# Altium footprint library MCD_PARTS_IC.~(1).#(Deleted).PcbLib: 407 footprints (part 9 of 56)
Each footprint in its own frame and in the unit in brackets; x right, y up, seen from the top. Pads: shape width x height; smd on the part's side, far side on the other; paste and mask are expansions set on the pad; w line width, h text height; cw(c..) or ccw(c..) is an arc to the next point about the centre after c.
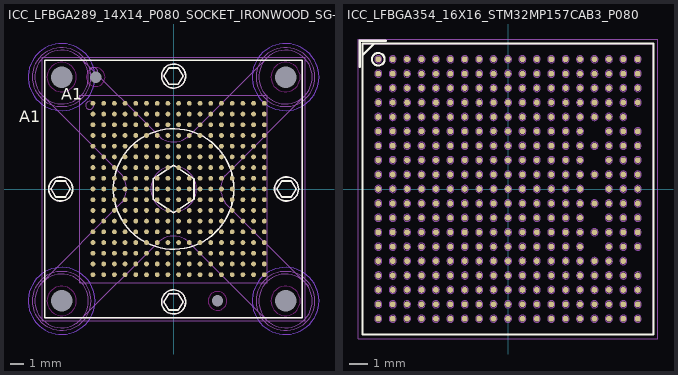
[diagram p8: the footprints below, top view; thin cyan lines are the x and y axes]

## ICC_LFBGA289_14X14_P080_SOCKET_IRONWOOD_SG-BGA-6112MF [mm] "MCD-02237"
height 8.25
pads (295):
  round 0.36 smd mask+0.05: A1(-6.025,6.4) A2(-5.225,6.4) A3(-4.425,6.4) A4(-3.625,6.4) A5(-2.825,6.4) A6(-2.025,6.4) A7(-1.225,6.4) A8(-0.425,6.4) A9(0.375,6.4) A10(1.175,6.4) A11(1.975,6.4) A12(2.775,6.4) A13(3.575,6.4) A14(4.375,6.4) A15(5.175,6.4) A16(5.975,6.4) A17(6.775,6.4) B1(-6.025,5.6) B2(-5.225,5.6) B3(-4.425,5.6) B4(-3.625,5.6) B5(-2.825,5.6) B6(-2.025,5.6) B7(-1.225,5.6) B8(-0.425,5.6) B9(0.375,5.6) B10(1.175,5.6) B11(1.975,5.6) B12(2.775,5.6) B13(3.575,5.6) B14(4.375,5.6) B15(5.175,5.6) B16(5.975,5.6) B17(6.775,5.6) C1(-6.025,4.8) C2(-5.225,4.8) C3(-4.425,4.8) C4(-3.625,4.8) C5(-2.825,4.8) C6(-2.025,4.8) C7(-1.225,4.8) C8(-0.425,4.8) C9(0.375,4.8) C10(1.175,4.8) C11(1.975,4.8) C12(2.775,4.8) C13(3.575,4.8) C14(4.375,4.8) C15(5.175,4.8) C16(5.975,4.8) C17(6.775,4.8) D1(-6.025,4) D2(-5.225,4) D3(-4.425,4) D4(-3.625,4) D5(-2.825,4) D6(-2.025,4) D7(-1.225,4) D8(-0.425,4) D9(0.375,4) D10(1.175,4) D11(1.975,4) D12(2.775,4) D13(3.575,4) D14(4.375,4) D15(5.175,4) D16(5.975,4) D17(6.775,4) E1(-6.025,3.2) E2(-5.225,3.2) E3(-4.425,3.2) E4(-3.625,3.2) E5(-2.825,3.2) E6(-2.025,3.2) E7(-1.225,3.2) E8(-0.425,3.2) E9(0.375,3.2) E10(1.175,3.2) E11(1.975,3.2) E12(2.775,3.2) E13(3.575,3.2) E14(4.375,3.2) E15(5.175,3.2) E16(5.975,3.2) E17(6.775,3.2) F1(-6.025,2.4) F2(-5.225,2.4) F3(-4.425,2.4) F4(-3.625,2.4) F5(-2.825,2.4) F6(-2.025,2.4) F7(-1.225,2.4) F8(-0.425,2.4) F9(0.375,2.4) F10(1.175,2.4) F11(1.975,2.4) F12(2.775,2.4) F13(3.575,2.4) F14(4.375,2.4) F15(5.175,2.4) F16(5.975,2.4) F17(6.775,2.4) G1(-6.025,1.6) G2(-5.225,1.6) G3(-4.425,1.6) G4(-3.625,1.6) G5(-2.825,1.6) G6(-2.025,1.6) G7(-1.225,1.6) G8(-0.425,1.6) G9(0.375,1.6) G10(1.175,1.6) G11(1.975,1.6) G12(2.775,1.6) G13(3.575,1.6) G14(4.375,1.6) G15(5.175,1.6) G16(5.975,1.6) G17(6.775,1.6) H1(-6.025,0.8) H2(-5.225,0.8) H3(-4.425,0.8) H4(-3.625,0.8) H5(-2.825,0.8) H6(-2.025,0.8) H7(-1.225,0.8) H8(-0.425,0.8) H9(0.375,0.8) H10(1.175,0.8) H11(1.975,0.8) H12(2.775,0.8) H13(3.575,0.8) H14(4.375,0.8) H15(5.175,0.8) H16(5.975,0.8) H17(6.775,0.8) J1(-6.025,0) J2(-5.225,0) J3(-4.425,0) J4(-3.625,0) J5(-2.825,0) J6(-2.025,0) J7(-1.225,0) J8(-0.425,0) J9(0.375,0) J10(1.175,0) J11(1.975,0) J12(2.775,0) J13(3.575,0) J14(4.375,0) J15(5.175,0) J16(5.975,0) J17(6.775,0) K1(-6.025,-0.8) K2(-5.225,-0.8) K3(-4.425,-0.8) K4(-3.625,-0.8) K5(-2.825,-0.8) K6(-2.025,-0.8) K7(-1.225,-0.8) K8(-0.425,-0.8) K9(0.375,-0.8) K10(1.175,-0.8) K11(1.975,-0.8) K12(2.775,-0.8) K13(3.575,-0.8) K14(4.375,-0.8) K15(5.175,-0.8) K16(5.975,-0.8) K17(6.775,-0.8) L1(-6.025,-1.6) L2(-5.225,-1.6) L3(-4.425,-1.6) L4(-3.625,-1.6) L5(-2.825,-1.6) L6(-2.025,-1.6) L7(-1.225,-1.6) L8(-0.425,-1.6) L9(0.375,-1.6) L10(1.175,-1.6) L11(1.975,-1.6) L12(2.775,-1.6) L13(3.575,-1.6) L14(4.375,-1.6) L15(5.175,-1.6) L16(5.975,-1.6) L17(6.775,-1.6) M1(-6.025,-2.4) M2(-5.225,-2.4) M3(-4.425,-2.4) M4(-3.625,-2.4) M5(-2.825,-2.4) M6(-2.025,-2.4) M7(-1.225,-2.4) M8(-0.425,-2.4) M9(0.375,-2.4) M10(1.175,-2.4) M11(1.975,-2.4) M12(2.775,-2.4) M13(3.575,-2.4) M14(4.375,-2.4) M15(5.175,-2.4) M16(5.975,-2.4) M17(6.775,-2.4) N1(-6.025,-3.2) N2(-5.225,-3.2) N3(-4.425,-3.2) N4(-3.625,-3.2) N5(-2.825,-3.2) N6(-2.025,-3.2) N7(-1.225,-3.2) N8(-0.425,-3.2) N9(0.375,-3.2) N10(1.175,-3.2) N11(1.975,-3.2) N12(2.775,-3.2) N13(3.575,-3.2) N14(4.375,-3.2) N15(5.175,-3.2) N16(5.975,-3.2) N17(6.775,-3.2) P1(-6.025,-4) P2(-5.225,-4) P3(-4.425,-4) P4(-3.625,-4) P5(-2.825,-4) P6(-2.025,-4) P7(-1.225,-4) P8(-0.425,-4) P9(0.375,-4) P10(1.175,-4) P11(1.975,-4) P12(2.775,-4) P13(3.575,-4) P14(4.375,-4) P15(5.175,-4) P16(5.975,-4) P17(6.775,-4) R1(-6.025,-4.8) R2(-5.225,-4.8) R3(-4.425,-4.8) R4(-3.625,-4.8) R5(-2.825,-4.8) R6(-2.025,-4.8) R7(-1.225,-4.8) R8(-0.425,-4.8) R9(0.375,-4.8) R10(1.175,-4.8) R11(1.975,-4.8) R12(2.775,-4.8) R13(3.575,-4.8) R14(4.375,-4.8) R15(5.175,-4.8) R16(5.975,-4.8) R17(6.775,-4.8) T1(-6.025,-5.6) T2(-5.225,-5.6) T3(-4.425,-5.6) T4(-3.625,-5.6) T5(-2.825,-5.6) T6(-2.025,-5.6) T7(-1.225,-5.6) T8(-0.425,-5.6) T9(0.375,-5.6) T10(1.175,-5.6) T11(1.975,-5.6) T12(2.775,-5.6) T13(3.575,-5.6) T14(4.375,-5.6) T15(5.175,-5.6) T16(5.975,-5.6) T17(6.775,-5.6) U1(-6.025,-6.4) U2(-5.225,-6.4) U3(-4.425,-6.4) U4(-3.625,-6.4) U5(-2.825,-6.4) U6(-2.025,-6.4) U7(-1.225,-6.4) U8(-0.425,-6.4) U9(0.375,-6.4) U10(1.175,-6.4) U11(1.975,-6.4) U12(2.775,-6.4) U13(3.575,-6.4) U14(4.375,-6.4) U15(5.175,-6.4) U16(5.975,-6.4) u17(6.775,-6.4)
  round 0 hole 1.61 unplated mask+0.05: NPTH1(-8.363,8.363) NPTH2(8.363,8.363) NPTH3(8.363,-8.363) NPTH4(-8.363,-8.363)
  round 0 hole 0.85 unplated mask+0.05: NPTH5(3.283,-8.363) NPTH6(-5.823,8.363)
Bottom Layer keep-out:
  circle w0.01: c-8.363,-8.363 r2.5
  circle w0.01: c8.363,-8.363 r2.5
  circle w0.01: c8.363,8.363 r2.5
  circle w0.01: c-8.362,8.362 r2.5
Top Overlay:
  circle w0.12: c0,8.437 r0.9
  circle w0.12: c8.438,0 r0.9
  circle w0.12: c0,-8.438 r0.9
  circle w0.12: c-8.438,0 r0.9
  circle w0.12: c0,0 r4.5
  lines w0.12: -9.613,-9.613 -9.613,9.613 9.613,9.613 9.613,-9.613 -9.613,-9.613 ; -9.158,0 -8.798,-0.6 -8.078,-0.6 -7.718,0 -8.078,0.6 -8.798,0.6 -9.158,0 ; -1.524,-0.762 -1.524,0.762 0,1.778 1.524,0.762 1.524,-0.762 0,-1.778 -1.524,-0.762 ; -0.72,-8.438 -0.36,-9.038 0.36,-9.038 0.72,-8.438 0.36,-7.838 -0.36,-7.838 -0.72,-8.438 ; -0.72,8.437 -0.36,9.037 0.36,9.037 0.72,8.437 0.36,7.837 -0.36,7.837 -0.72,8.437 ; 7.718,0 8.078,-0.6 8.798,-0.6 9.158,0 8.798,0.6 8.078,0.6 7.718,0
  text "A1" at -11.55,4.675 h1.5
  text "A1" at -8.4,6.375 h1.5
Bottom Overlay:
  circle w0.12: c8.363,8.363 r2.5
  circle w0.12: c8.362,-8.362 r2.5
  circle w0.12: c-8.362,-8.362 r2.5
  circle w0.12: c-8.363,8.363 r2.5
Keep-Out Layer:
  circle w0.01: c3.283,-8.363 r0.7
  circle w0.01: c-8.363,-8.363 r1.1
  circle w0.01: c8.362,-8.362 r1.1
  circle w0.01: c8.363,8.363 r1.1
  circle w0.01: c-8.362,8.362 r1.1
  circle w0.01: c-5.823,8.363 r0.7
M14-Top Assembly:
  circle w0.01: c-6.275,6.25 r0.3
  circle w0.01: c-5.975,8.775 r0.3
  circle w0.01: c0,8.437 r0.9
  circle w0.01: c8.438,0 r0.9
  circle w0.01: c0,-8.438 r0.9
  circle w0.01: c-8.438,0 r0.9
  circle w0.01: c0,0 r4.5
  lines w0.01: -9.613,-9.613 -9.613,9.613 9.613,9.613 9.613,3.562 9.613,-9.613 -9.613,-9.613 ; -9.158,0 -8.798,0.6 -8.078,0.6 -7.718,0 -8.078,-0.6 -8.798,-0.6 -9.158,0 ; -7,-7 -7,7 7,7 7,-7 -7,-7 ; -1.524,-0.762 -1.524,0.762 0,1.778 1.524,0.762 1.524,-0.762 0,-1.778 -1.524,-0.762 ; -0.72,-8.438 -0.36,-7.838 0.36,-7.838 0.72,-8.438 0.36,-9.038 -0.36,-9.038 -0.72,-8.438 ; -0.72,8.437 -0.36,7.837 0.36,7.837 0.72,8.437 0.36,9.037 -0.36,9.037 -0.72,8.437 ; 7.718,0 8.078,0.6 8.798,0.6 9.158,0 8.798,-0.6 8.078,-0.6 7.718,0
  text "'.Designator'" at 0,0 h0.75
M15-Bottom Assembly:
  circle w0.01: c8.362,8.362 r2
  circle w0.01: c8.363,-8.363 r2
  circle w0.01: c-8.362,-8.362 r2
  circle w0.01: c-8.362,8.362 r2
  lines w0.01: -10.044,7.235 -3.82,1.011 ; -9.929,-7.075 -3.82,-0.967 ; -7.235,-10.044 -1.011,-3.82 ; -7.075,9.929 -0.967,3.82 ; -3.848,1.029 cw(c-5.325,0) -3.826,-0.996 ; -1.029,-3.848 cw(c0,-5.325) 0.996,-3.826 ; -0.996,3.826 ccw(c0,5.325) 1.029,3.848 ; 0.967,-3.82 7.075,-9.929 ; 1.011,3.82 7.235,10.044 ; 3.82,-1.011 10.044,-7.235 ; 3.82,0.967 9.928,7.075 ; 3.826,0.996 ccw(c5.325,0) 3.848,-1.029
M16-Top Courtyard:
  lines w0.01: -9.825,-9.825 9.825,-9.825 9.825,9.825 -9.825,9.825 -9.825,-9.825
M17-Bottom Courtyard:
  circle w0.01: c-8.362,-8.362 r2.2
  circle w0.01: c8.362,-8.362 r2.2
  circle w0.01: c8.362,8.362 r2.2
  circle w0.01: c-8.362,8.362 r2.2
  circle w0.01: c0,0 r1.7
3D body: height 5, standoff 0, extent -9.613,-9.613 9.613,9.613
3D body: height 9.86, standoff 9.85, extent -1.025,-1.212 1.025,1.213
3D body: height 9.85, standoff 1.6, extent -2.5,-2.497 2.5,2.497
3D body: height 6.01, standoff 6, extent -0.72,-9.038 0.72,-7.838
3D body: height 6, standoff 5, extent -0.893,-9.336 0.9,-7.539
3D body: height 6.01, standoff 6, extent 7.717,-0.6 9.158,0.6
3D body: height 6, standoff 5, extent 7.545,-0.898 9.338,0.898
3D body: height 6.01, standoff 6, extent -0.72,7.837 0.72,9.037
3D body: height 6, standoff 5, extent -0.893,7.539 0.9,9.336
3D body: height 6.01, standoff 6, extent -9.158,-0.6 -7.718,0.6
3D body: height 6, standoff 5, extent -9.33,-0.898 -7.537,0.898
3D body: height -4.1, standoff -6.6, extent -10.044,-10.044 10.044,10.044
3D body: height -1.6, standoff -6.6, extent -1.5,-1.5 1.5,1.5
3D body: height -1.6, standoff -6.6, extent -10.375,-8.363 -6.362,-6.35
3D body: height -1.6, standoff -6.6, extent -10.375,-10.363 -6.363,-8.35
3D body: height -1.6, standoff -6.6, extent 6.35,-8.363 10.363,-6.35
3D body: height -1.6, standoff -6.6, extent 6.35,-10.363 10.362,-8.35
3D body: height -1.6, standoff -6.6, extent 6.35,8.362 10.363,10.375
3D body: height -1.6, standoff -6.6, extent 6.35,6.362 10.362,8.375
3D body: height -1.6, standoff -6.6, extent -10.375,6.362 -6.363,8.375
3D body: height -1.6, standoff -6.6, extent -10.375,8.362 -6.362,10.375

## ICC_LFBGA354_16X16_STM32MP157CAB3_P080 [mm] "MCD-01805"
height 1.29
pads (354):
  round 0.32 smd paste+0 mask+0.05: A1(-7.2,7.2) A2(-6.4,7.2) A3(-5.6,7.2) A4(-4.8,7.2) A5(-4,7.2) A6(-3.2,7.2) A7(-2.4,7.2) A8(-1.6,7.2) A9(-0.8,7.2) A10(0,7.2) A11(0.8,7.2) A12(1.6,7.2) A13(2.4,7.2) A14(3.2,7.2) A15(4,7.2) A16(4.8,7.2) A17(5.6,7.2) A18(6.4,7.2) A19(7.2,7.2) B1(-7.2,6.4) B2(-6.4,6.4) B3(-5.6,6.4) B4(-4.8,6.4) B5(-4,6.4) B6(-3.2,6.4) B7(-2.4,6.4) B8(-1.6,6.4) B9(-0.8,6.4) B10(0,6.4) B11(0.8,6.4) B12(1.6,6.4) B13(2.4,6.4) B14(3.2,6.4) B15(4,6.4) B16(4.8,6.4) B17(5.6,6.4) B18(6.4,6.4) B19(7.2,6.4) C1(-7.2,5.6) C2(-6.4,5.6) C3(-5.6,5.6) C4(-4.8,5.6) C5(-4,5.6) C6(-3.2,5.6) C7(-2.4,5.6) C8(-1.6,5.6) C9(-0.8,5.6) C10(0,5.6) C11(0.8,5.6) C12(1.6,5.6) C13(2.4,5.6) C14(3.2,5.6) C15(4,5.6) C16(4.8,5.6) C17(5.6,5.6) C18(6.4,5.6) C19(7.2,5.6) D1(-7.2,4.8) D2(-6.4,4.8) D3(-5.6,4.8) D4(-4.8,4.8) D5(-4,4.8) D6(-3.2,4.8) D7(-2.4,4.8) D8(-1.6,4.8) D9(-0.8,4.8) D10(0,4.8) D11(0.8,4.8) D12(1.6,4.8) D13(2.4,4.8) D14(3.2,4.8) D15(4,4.8) D16(4.8,4.8) D17(5.6,4.8) D18(6.4,4.8) D19(7.2,4.8) E1(-7.2,4) E2(-6.4,4) E3(-5.6,4) E4(-4.8,4) E5(-4,4) E6(-3.2,4) E7(-2.4,4) E8(-1.6,4) E9(-0.8,4) E10(0,4) E11(0.8,4) E12(1.6,4) E13(2.4,4) E14(3.2,4) E15(4,4) E16(4.8,4) E17(5.6,4) E18(6.4,4) F1(-7.2,3.2) F2(-6.4,3.2) F3(-5.6,3.2) F4(-4.8,3.2) F5(-4,3.2) F6(-3.2,3.2) F7(-2.4,3.2) F8(-1.6,3.2) F9(-0.8,3.2) F10(0,3.2) F11(0.8,3.2) F12(1.6,3.2) F13(2.4,3.2) F14(3.2,3.2) F15(4,3.2) F17(5.6,3.2) F18(6.4,3.2) F19(7.2,3.2) G1(-7.2,2.4) G2(-6.4,2.4) G3(-5.6,2.4) G4(-4.8,2.4) G5(-4,2.4) G6(-3.2,2.4) G7(-2.4,2.4) G8(-1.6,2.4) G9(-0.8,2.4) G10(0,2.4) G11(0.8,2.4) G12(1.6,2.4) G13(2.4,2.4) G14(3.2,2.4) G15(4,2.4) G16(4.8,2.4) G17(5.6,2.4) G18(6.4,2.4) G19(7.2,2.4) H1(-7.2,1.6) H2(-6.4,1.6) H3(-5.6,1.6) H4(-4.8,1.6) H5(-4,1.6) H6(-3.2,1.6) H7(-2.4,1.6) H8(-1.6,1.6) H9(-0.8,1.6) H10(0,1.6) H11(0.8,1.6) H12(1.6,1.6) H13(2.4,1.6) H14(3.2,1.6) H15(4,1.6) H17(5.6,1.6) H18(6.4,1.6) H19(7.2,1.6) J1(-7.2,0.8) J2(-6.4,0.8) J3(-5.6,0.8) J4(-4.8,0.8) J5(-4,0.8) J6(-3.2,0.8) J7(-2.4,0.8) J8(-1.6,0.8) J9(-0.8,0.8) J10(0,0.8) J11(0.8,0.8) J12(1.6,0.8) J13(2.4,0.8) J14(3.2,0.8) J15(4,0.8) J16(4.8,0.8) J17(5.6,0.8) J18(6.4,0.8) J19(7.2,0.8) K1(-7.2,0) K2(-6.4,0) K3(-5.6,0) K4(-4.8,0) K5(-4,0) K6(-3.2,0) K7(-2.4,0) K8(-1.6,0) K9(-0.8,0) K10(0,0) K11(0.8,0) K12(1.6,0) K13(2.4,0) K14(3.2,0) K15(4,0) K17(5.6,0) K18(6.4,0) K19(7.2,0) L1(-7.2,-0.8) L2(-6.4,-0.8) L3(-5.6,-0.8) L4(-4.8,-0.8) L5(-4,-0.8) L6(-3.2,-0.8) L7(-2.4,-0.8) L8(-1.6,-0.8) L9(-0.8,-0.8) L10(0,-0.8) L11(0.8,-0.8) L12(1.6,-0.8) L13(2.4,-0.8) L14(3.2,-0.8) L15(4,-0.8) L16(4.8,-0.8) L17(5.6,-0.8) L18(6.4,-0.8) L19(7.2,-0.8) M1(-7.2,-1.6) M2(-6.4,-1.6) M3(-5.6,-1.6) M4(-4.8,-1.6) M5(-4,-1.6) M6(-3.2,-1.6) M7(-2.4,-1.6) M8(-1.6,-1.6) M9(-0.8,-1.6) M10(0,-1.6) M11(0.8,-1.6) M12(1.6,-1.6) M13(2.4,-1.6) M14(3.2,-1.6) M15(4,-1.6) M17(5.6,-1.6) M18(6.4,-1.6) M19(7.2,-1.6) N1(-7.2,-2.4) N2(-6.4,-2.4) N3(-5.6,-2.4) N4(-4.8,-2.4) N5(-4,-2.4) N6(-3.2,-2.4) N7(-2.4,-2.4) N8(-1.6,-2.4) N9(-0.8,-2.4) N10(0,-2.4) N11(0.8,-2.4) N12(1.6,-2.4) N13(2.4,-2.4) N14(3.2,-2.4) N15(4,-2.4) N16(4.8,-2.4) N17(5.6,-2.4) N18(6.4,-2.4) N19(7.2,-2.4) P1(-7.2,-3.2) P2(-6.4,-3.2) P3(-5.6,-3.2) P4(-4.8,-3.2) P5(-4,-3.2) P6(-3.2,-3.2) P7(-2.4,-3.2) P8(-1.6,-3.2) P9(-0.8,-3.2) P10(0,-3.2) P11(0.8,-3.2) P12(1.6,-3.2) P13(2.4,-3.2) P14(3.2,-3.2) P15(4,-3.2) P17(5.6,-3.2) P18(6.4,-3.2) P19(7.2,-3.2) R1(-7.2,-4) R2(-6.4,-4) R3(-5.6,-4) R4(-4.8,-4) R5(-4,-4) R6(-3.2,-4) R7(-2.4,-4) R8(-1.6,-4) R9(-0.8,-4) R10(0,-4) R11(0.8,-4) R12(1.6,-4) R13(2.4,-4) R14(3.2,-4) R15(4,-4) R16(4.8,-4) R17(5.6,-4) R18(6.4,-4) T1(-7.2,-4.8) T2(-6.4,-4.8) T3(-5.6,-4.8) T4(-4.8,-4.8) T5(-4,-4.8) T6(-3.2,-4.8) T7(-2.4,-4.8) T8(-1.6,-4.8) T9(-0.8,-4.8) T10(0,-4.8) T11(0.8,-4.8) T12(1.6,-4.8) T13(2.4,-4.8) T14(3.2,-4.8) T15(4,-4.8) T16(4.8,-4.8) T17(5.6,-4.8) T18(6.4,-4.8) T19(7.2,-4.8) U1(-7.2,-5.6) U2(-6.4,-5.6) U3(-5.6,-5.6) U4(-4.8,-5.6) U5(-4,-5.6) U6(-3.2,-5.6) U7(-2.4,-5.6) U8(-1.6,-5.6) U9(-0.8,-5.6) U10(0,-5.6) U11(0.8,-5.6) U12(1.6,-5.6) U13(2.4,-5.6) U14(3.2,-5.6) U15(4,-5.6) U16(4.8,-5.6) U17(5.6,-5.6) U18(6.4,-5.6) U19(7.2,-5.6) V1(-7.2,-6.4) V2(-6.4,-6.4) V3(-5.6,-6.4) V4(-4.8,-6.4) V5(-4,-6.4) V6(-3.2,-6.4) V7(-2.4,-6.4) V8(-1.6,-6.4) V9(-0.8,-6.4) V10(0,-6.4) V11(0.8,-6.4) V12(1.6,-6.4) V13(2.4,-6.4) V14(3.2,-6.4) V15(4,-6.4) V16(4.8,-6.4) V17(5.6,-6.4) V18(6.4,-6.4) V19(7.2,-6.4) W1(-7.2,-7.2) W2(-6.4,-7.2) W3(-5.6,-7.2) W4(-4.8,-7.2) W5(-4,-7.2) W6(-3.2,-7.2) W7(-2.4,-7.2) W8(-1.6,-7.2) W9(-0.8,-7.2) W10(0,-7.2) W11(0.8,-7.2) W12(1.6,-7.2) W13(2.4,-7.2) W14(3.2,-7.2) W15(4,-7.2) W16(4.8,-7.2) W17(5.6,-7.2) W18(6.4,-7.2) W19(7.2,-7.2)
Top Overlay:
  circle w0.12: c-7.2,7.2 r0.35
  lines w0.12: -8.225,6.775 -8.225,8.225 -6.775,8.225 ; -8.075,7.42 -7.42,8.075 ; -8.075,-8.075 -8.075,8.075 8.075,8.075 8.075,-8.075 -8.075,-8.075
M14-Top Assembly:
  drawing of 358 lines, arcs and shapes, not listed
  text "A1" at -7.45,7 h0.4
  text "'.Designator'" at -2,-0.5 h0.75
M16-Top Courtyard:
  lines w0.01: -8.325,-8.325 8.325,-8.325 8.325,8.325 -8.325,8.325 -8.325,-8.325
3D body: height 0.36, standoff -0.04, extent 4.601,-7.397 5,-7.003
3D body: height 0.36, standoff -0.04, extent 5.401,-7.397 5.8,-7.003
3D body: height 0.36, standoff -0.04, extent 6.201,-7.397 6.6,-7.003
3D body: height 0.36, standoff -0.04, extent 7.001,-7.397 7.4,-7.003
3D body: height 0.36, standoff -0.04, extent 4.601,-2.597 5,-2.203
3D body: height 0.36, standoff -0.04, extent 5.401,-2.597 5.8,-2.203
3D body: height 0.36, standoff -0.04, extent 6.201,-2.597 6.6,-2.203
3D body: height 0.36, standoff -0.04, extent 7.001,-2.597 7.4,-2.203
3D body: height 0.36, standoff -0.04, extent 7.001,-3.397 7.4,-3.003
3D body: height 0.36, standoff -0.04, extent 6.201,-3.397 6.6,-3.003
3D body: height 0.36, standoff -0.04, extent 5.401,-3.397 5.8,-3.003
3D body: height 0.36, standoff -0.04, extent 6.201,-4.197 6.6,-3.803
3D body: height 0.36, standoff -0.04, extent 5.401,-4.197 5.8,-3.803
3D body: height 0.36, standoff -0.04, extent 4.601,-4.197 5,-3.803
3D body: height 0.36, standoff -0.04, extent 7.001,-4.997 7.4,-4.603
3D body: height 0.36, standoff -0.04, extent 6.201,-4.997 6.6,-4.603
3D body: height 0.36, standoff -0.04, extent 5.401,-4.997 5.8,-4.603
3D body: height 0.36, standoff -0.04, extent 4.601,-4.997 5,-4.603
3D body: height 0.36, standoff -0.04, extent 7.001,-5.797 7.4,-5.403
3D body: height 0.36, standoff -0.04, extent 6.201,-5.797 6.6,-5.403
3D body: height 0.36, standoff -0.04, extent 5.401,-5.797 5.8,-5.403
3D body: height 0.36, standoff -0.04, extent 4.601,-5.797 5,-5.403
3D body: height 0.36, standoff -0.04, extent 7.001,-6.597 7.4,-6.203
3D body: height 0.36, standoff -0.04, extent 6.201,-6.597 6.6,-6.203
3D body: height 0.36, standoff -0.04, extent 5.401,-6.597 5.8,-6.203
3D body: height 0.36, standoff -0.04, extent 4.601,-6.597 5,-6.203
3D body: height 0.36, standoff -0.04, extent 4.601,2.203 5,2.597
3D body: height 0.36, standoff -0.04, extent 5.401,2.203 5.8,2.597
3D body: height 0.36, standoff -0.04, extent 6.201,2.203 6.6,2.597
3D body: height 0.36, standoff -0.04, extent 7.001,2.203 7.4,2.597
3D body: height 0.36, standoff -0.04, extent 7.001,1.403 7.4,1.797
3D body: height 0.36, standoff -0.04, extent 6.201,1.403 6.6,1.797
3D body: height 0.36, standoff -0.04, extent 5.401,1.403 5.8,1.797
3D body: height 0.36, standoff -0.04, extent 7.001,0.603 7.4,0.997
3D body: height 0.36, standoff -0.04, extent 6.201,0.603 6.6,0.997
3D body: height 0.36, standoff -0.04, extent 5.401,0.603 5.8,0.997
3D body: height 0.36, standoff -0.04, extent 4.601,0.603 5,0.997
3D body: height 0.36, standoff -0.04, extent 7.001,-0.197 7.4,0.197
3D body: height 0.36, standoff -0.04, extent 6.201,-0.197 6.6,0.197
3D body: height 0.36, standoff -0.04, extent 5.401,-0.197 5.8,0.197
3D body: height 0.36, standoff -0.04, extent 7.001,-0.997 7.4,-0.603
3D body: height 0.36, standoff -0.04, extent 6.201,-0.997 6.6,-0.603
3D body: height 0.36, standoff -0.04, extent 5.401,-0.997 5.8,-0.603
3D body: height 0.36, standoff -0.04, extent 4.601,-0.997 5,-0.603
3D body: height 0.36, standoff -0.04, extent 7.001,-1.797 7.4,-1.403
3D body: height 0.36, standoff -0.04, extent 6.201,-1.797 6.6,-1.403
3D body: height 0.36, standoff -0.04, extent 5.401,-1.797 5.8,-1.403
3D body: height 0.36, standoff -0.04, extent 3.801,-7.397 4.2,-7.003
3D body: height 0.36, standoff -0.04, extent 3.001,-7.397 3.4,-7.003
3D body: height 0.36, standoff -0.04, extent 2.201,-7.397 2.6,-7.003
3D body: height 0.36, standoff -0.04, extent 1.401,-7.397 1.8,-7.003
3D body: height 0.36, standoff -0.04, extent 0.601,-7.397 1,-7.003
3D body: height 0.36, standoff -0.04, extent -3.399,-7.397 -3,-7.003
3D body: height 0.36, standoff -0.04, extent -2.599,-7.397 -2.2,-7.003
3D body: height 0.36, standoff -0.04, extent -1.799,-7.397 -1.4,-7.003
3D body: height 0.36, standoff -0.04, extent -0.999,-7.397 -0.6,-7.003
3D body: height 0.36, standoff -0.04, extent -0.199,-7.397 0.2,-7.003
3D body: height 0.36, standoff -0.04, extent -7.399,-7.397 -7,-7.003
3D body: height 0.36, standoff -0.04, extent -6.599,-7.397 -6.2,-7.003
3D body: height 0.36, standoff -0.04, extent -5.799,-7.397 -5.4,-7.003
3D body: height 0.36, standoff -0.04, extent -4.999,-7.397 -4.6,-7.003
3D body: height 0.36, standoff -0.04, extent -4.199,-7.397 -3.8,-7.003
3D body: height 0.36, standoff -0.04, extent 3.801,-2.597 4.2,-2.203
3D body: height 0.36, standoff -0.04, extent 3.001,-2.597 3.4,-2.203
3D body: height 0.36, standoff -0.04, extent 2.201,-2.597 2.6,-2.203
3D body: height 0.36, standoff -0.04, extent 1.401,-2.597 1.8,-2.203
3D body: height 0.36, standoff -0.04, extent 0.601,-2.597 1,-2.203
3D body: height 0.36, standoff -0.04, extent -3.399,-2.597 -3,-2.203
3D body: height 0.36, standoff -0.04, extent -2.599,-2.597 -2.2,-2.203
3D body: height 0.36, standoff -0.04, extent -1.799,-2.597 -1.4,-2.203
3D body: height 0.36, standoff -0.04, extent -0.999,-2.597 -0.6,-2.203
3D body: height 0.36, standoff -0.04, extent -0.199,-2.597 0.2,-2.203
3D body: height 0.36, standoff -0.04, extent -7.399,-2.597 -7,-2.203
3D body: height 0.36, standoff -0.04, extent -6.599,-2.597 -6.2,-2.203
3D body: height 0.36, standoff -0.04, extent -5.799,-2.597 -5.4,-2.203
3D body: height 0.36, standoff -0.04, extent -4.999,-2.597 -4.6,-2.203
3D body: height 0.36, standoff -0.04, extent -4.199,-2.597 -3.8,-2.203
3D body: height 0.36, standoff -0.04, extent -4.199,-3.397 -3.8,-3.003
3D body: height 0.36, standoff -0.04, extent -4.999,-3.397 -4.6,-3.003
3D body: height 0.36, standoff -0.04, extent -5.799,-3.397 -5.4,-3.003
3D body: height 0.36, standoff -0.04, extent -6.599,-3.397 -6.2,-3.003
3D body: height 0.36, standoff -0.04, extent -7.399,-3.397 -7,-3.003
3D body: height 0.36, standoff -0.04, extent -0.199,-3.397 0.2,-3.003
3D body: height 0.36, standoff -0.04, extent -0.999,-3.397 -0.6,-3.003
3D body: height 0.36, standoff -0.04, extent -1.799,-3.397 -1.4,-3.003
3D body: height 0.36, standoff -0.04, extent -2.599,-3.397 -2.2,-3.003
3D body: height 0.36, standoff -0.04, extent -3.399,-3.397 -3,-3.003
3D body: height 0.36, standoff -0.04, extent 0.601,-3.397 1,-3.003
3D body: height 0.36, standoff -0.04, extent 1.401,-3.397 1.8,-3.003
3D body: height 0.36, standoff -0.04, extent 2.201,-3.397 2.6,-3.003
3D body: height 0.36, standoff -0.04, extent 3.001,-3.397 3.4,-3.003
3D body: height 0.36, standoff -0.04, extent 3.801,-3.397 4.2,-3.003
3D body: height 0.36, standoff -0.04, extent -4.199,-4.197 -3.8,-3.803
3D body: height 0.36, standoff -0.04, extent -4.999,-4.197 -4.6,-3.803
3D body: height 0.36, standoff -0.04, extent -5.799,-4.197 -5.4,-3.803
3D body: height 0.36, standoff -0.04, extent -6.599,-4.197 -6.2,-3.803
3D body: height 0.36, standoff -0.04, extent -7.399,-4.197 -7,-3.803
3D body: height 0.36, standoff -0.04, extent -0.199,-4.197 0.2,-3.803
3D body: height 0.36, standoff -0.04, extent -0.999,-4.197 -0.6,-3.803
3D body: height 0.36, standoff -0.04, extent -1.799,-4.197 -1.4,-3.803
3D body: height 0.36, standoff -0.04, extent -2.599,-4.197 -2.2,-3.803
3D body: height 0.36, standoff -0.04, extent -3.399,-4.197 -3,-3.803
3D body: height 0.36, standoff -0.04, extent 0.601,-4.197 1,-3.803
3D body: height 0.36, standoff -0.04, extent 1.401,-4.197 1.8,-3.803
3D body: height 0.36, standoff -0.04, extent 2.201,-4.197 2.6,-3.803
3D body: height 0.36, standoff -0.04, extent 3.001,-4.197 3.4,-3.803
3D body: height 0.36, standoff -0.04, extent 3.801,-4.197 4.2,-3.803
3D body: height 0.36, standoff -0.04, extent -4.199,-4.997 -3.8,-4.603
3D body: height 0.36, standoff -0.04, extent -4.999,-4.997 -4.6,-4.603
3D body: height 0.36, standoff -0.04, extent -5.799,-4.997 -5.4,-4.603
3D body: height 0.36, standoff -0.04, extent -6.599,-4.997 -6.2,-4.603
3D body: height 0.36, standoff -0.04, extent -7.399,-4.997 -7,-4.603
3D body: height 0.36, standoff -0.04, extent -0.199,-4.997 0.2,-4.603
3D body: height 0.36, standoff -0.04, extent -0.999,-4.997 -0.6,-4.603
3D body: height 0.36, standoff -0.04, extent -1.799,-4.997 -1.4,-4.603
3D body: height 0.36, standoff -0.04, extent -2.599,-4.997 -2.2,-4.603
3D body: height 0.36, standoff -0.04, extent -3.399,-4.997 -3,-4.603
3D body: height 0.36, standoff -0.04, extent 0.601,-4.997 1,-4.603
3D body: height 0.36, standoff -0.04, extent 1.401,-4.997 1.8,-4.603
3D body: height 0.36, standoff -0.04, extent 2.201,-4.997 2.6,-4.603
3D body: height 0.36, standoff -0.04, extent 3.001,-4.997 3.4,-4.603
3D body: height 0.36, standoff -0.04, extent 3.801,-4.997 4.2,-4.603
3D body: height 0.36, standoff -0.04, extent -4.199,-5.797 -3.8,-5.403
3D body: height 0.36, standoff -0.04, extent -4.999,-5.797 -4.6,-5.403
3D body: height 0.36, standoff -0.04, extent -5.799,-5.797 -5.4,-5.403
3D body: height 0.36, standoff -0.04, extent -6.599,-5.797 -6.2,-5.403
3D body: height 0.36, standoff -0.04, extent -7.399,-5.797 -7,-5.403
3D body: height 0.36, standoff -0.04, extent -0.199,-5.797 0.2,-5.403
3D body: height 0.36, standoff -0.04, extent -0.999,-5.797 -0.6,-5.403
3D body: height 0.36, standoff -0.04, extent -1.799,-5.797 -1.4,-5.403
3D body: height 0.36, standoff -0.04, extent -2.599,-5.797 -2.2,-5.403
3D body: height 0.36, standoff -0.04, extent -3.399,-5.797 -3,-5.403
3D body: height 0.36, standoff -0.04, extent 0.601,-5.797 1,-5.403
3D body: height 0.36, standoff -0.04, extent 1.401,-5.797 1.8,-5.403
3D body: height 0.36, standoff -0.04, extent 2.201,-5.797 2.6,-5.403
3D body: height 0.36, standoff -0.04, extent 3.001,-5.797 3.4,-5.403
3D body: height 0.36, standoff -0.04, extent 3.801,-5.797 4.2,-5.403
3D body: height 0.36, standoff -0.04, extent -4.199,-6.597 -3.8,-6.203
3D body: height 0.36, standoff -0.04, extent -4.999,-6.597 -4.6,-6.203
3D body: height 0.36, standoff -0.04, extent -5.799,-6.597 -5.4,-6.203
3D body: height 0.36, standoff -0.04, extent -6.599,-6.597 -6.2,-6.203
3D body: height 0.36, standoff -0.04, extent -7.399,-6.597 -7,-6.203
3D body: height 0.36, standoff -0.04, extent -0.199,-6.597 0.2,-6.203
3D body: height 0.36, standoff -0.04, extent -0.999,-6.597 -0.6,-6.203
3D body: height 0.36, standoff -0.04, extent -1.799,-6.597 -1.4,-6.203
3D body: height 0.36, standoff -0.04, extent -2.599,-6.597 -2.2,-6.203
3D body: height 0.36, standoff -0.04, extent -3.399,-6.597 -3,-6.203
3D body: height 0.36, standoff -0.04, extent 0.601,-6.597 1,-6.203
3D body: height 0.36, standoff -0.04, extent 1.401,-6.597 1.8,-6.203
3D body: height 0.36, standoff -0.04, extent 2.201,-6.597 2.6,-6.203
3D body: height 0.36, standoff -0.04, extent 3.001,-6.597 3.4,-6.203
3D body: height 0.36, standoff -0.04, extent 3.801,-6.597 4.2,-6.203
3D body: height 0.36, standoff -0.04, extent 3.801,2.203 4.2,2.597
3D body: height 0.36, standoff -0.04, extent 3.001,2.203 3.4,2.597
3D body: height 0.36, standoff -0.04, extent 2.201,2.203 2.6,2.597
3D body: height 0.36, standoff -0.04, extent 1.401,2.203 1.8,2.597
3D body: height 0.36, standoff -0.04, extent 0.601,2.203 1,2.597
3D body: height 0.36, standoff -0.04, extent -3.399,2.203 -3,2.597
3D body: height 0.36, standoff -0.04, extent -2.599,2.203 -2.2,2.597
3D body: height 0.36, standoff -0.04, extent -1.799,2.203 -1.4,2.597
3D body: height 0.36, standoff -0.04, extent -0.999,2.203 -0.6,2.597
3D body: height 0.36, standoff -0.04, extent -0.199,2.203 0.2,2.597
3D body: height 0.36, standoff -0.04, extent -7.399,2.203 -7,2.597
3D body: height 0.36, standoff -0.04, extent -6.599,2.203 -6.2,2.597
3D body: height 0.36, standoff -0.04, extent -5.799,2.203 -5.4,2.597
3D body: height 0.36, standoff -0.04, extent -4.999,2.203 -4.6,2.597
3D body: height 0.36, standoff -0.04, extent -4.199,2.203 -3.8,2.597
3D body: height 0.36, standoff -0.04, extent -4.199,1.403 -3.8,1.797
3D body: height 0.36, standoff -0.04, extent -4.999,1.403 -4.6,1.797
3D body: height 0.36, standoff -0.04, extent -5.799,1.403 -5.4,1.797
3D body: height 0.36, standoff -0.04, extent -6.599,1.403 -6.2,1.797
3D body: height 0.36, standoff -0.04, extent -7.399,1.403 -7,1.797
3D body: height 0.36, standoff -0.04, extent -0.199,1.403 0.2,1.797
3D body: height 0.36, standoff -0.04, extent -0.999,1.403 -0.6,1.797
3D body: height 0.36, standoff -0.04, extent -1.799,1.403 -1.4,1.797
3D body: height 0.36, standoff -0.04, extent -2.599,1.403 -2.2,1.797
3D body: height 0.36, standoff -0.04, extent -3.399,1.403 -3,1.797
3D body: height 0.36, standoff -0.04, extent 0.601,1.403 1,1.797
3D body: height 0.36, standoff -0.04, extent 1.401,1.403 1.8,1.797
3D body: height 0.36, standoff -0.04, extent 2.201,1.403 2.6,1.797
3D body: height 0.36, standoff -0.04, extent 3.001,1.403 3.4,1.797
3D body: height 0.36, standoff -0.04, extent 3.801,1.403 4.2,1.797
3D body: height 0.36, standoff -0.04, extent -4.199,0.603 -3.8,0.997
3D body: height 0.36, standoff -0.04, extent -4.999,0.603 -4.6,0.997
3D body: height 0.36, standoff -0.04, extent -5.799,0.603 -5.4,0.997
3D body: height 0.36, standoff -0.04, extent -6.599,0.603 -6.2,0.997
3D body: height 0.36, standoff -0.04, extent -7.399,0.603 -7,0.997
3D body: height 0.36, standoff -0.04, extent -0.199,0.603 0.2,0.997
3D body: height 0.36, standoff -0.04, extent -0.999,0.603 -0.6,0.997
3D body: height 0.36, standoff -0.04, extent -1.799,0.603 -1.4,0.997
3D body: height 0.36, standoff -0.04, extent -2.599,0.603 -2.2,0.997
3D body: height 0.36, standoff -0.04, extent -3.399,0.603 -3,0.997
3D body: height 0.36, standoff -0.04, extent 0.601,0.603 1,0.997
3D body: height 0.36, standoff -0.04, extent 1.401,0.603 1.8,0.997
3D body: height 0.36, standoff -0.04, extent 2.201,0.603 2.6,0.997
3D body: height 0.36, standoff -0.04, extent 3.001,0.603 3.4,0.997
3D body: height 0.36, standoff -0.04, extent 3.801,0.603 4.2,0.997
3D body: height 0.36, standoff -0.04, extent -4.199,-0.197 -3.8,0.197
3D body: height 0.36, standoff -0.04, extent -4.999,-0.197 -4.6,0.197
3D body: height 0.36, standoff -0.04, extent -5.799,-0.197 -5.4,0.197
3D body: height 0.36, standoff -0.04, extent -6.599,-0.197 -6.2,0.197
3D body: height 0.36, standoff -0.04, extent -7.399,-0.197 -7,0.197
3D body: height 0.36, standoff -0.04, extent -0.199,-0.197 0.2,0.197
3D body: height 0.36, standoff -0.04, extent -0.999,-0.197 -0.6,0.197
3D body: height 0.36, standoff -0.04, extent -1.799,-0.197 -1.4,0.197
3D body: height 0.36, standoff -0.04, extent -2.599,-0.197 -2.2,0.197
3D body: height 0.36, standoff -0.04, extent -3.399,-0.197 -3,0.197
3D body: height 0.36, standoff -0.04, extent 0.601,-0.197 1,0.197
3D body: height 0.36, standoff -0.04, extent 1.401,-0.197 1.8,0.197
3D body: height 0.36, standoff -0.04, extent 2.201,-0.197 2.6,0.197
3D body: height 0.36, standoff -0.04, extent 3.001,-0.197 3.4,0.197
3D body: height 0.36, standoff -0.04, extent 3.801,-0.197 4.2,0.197
3D body: height 0.36, standoff -0.04, extent -4.199,-0.997 -3.8,-0.603
3D body: height 0.36, standoff -0.04, extent -4.999,-0.997 -4.6,-0.603
3D body: height 0.36, standoff -0.04, extent -5.799,-0.997 -5.4,-0.603
3D body: height 0.36, standoff -0.04, extent -6.599,-0.997 -6.2,-0.603
3D body: height 0.36, standoff -0.04, extent -7.399,-0.997 -7,-0.603
3D body: height 0.36, standoff -0.04, extent -0.199,-0.997 0.2,-0.603
3D body: height 0.36, standoff -0.04, extent -0.999,-0.997 -0.6,-0.603
3D body: height 0.36, standoff -0.04, extent -1.799,-0.997 -1.4,-0.603
3D body: height 0.36, standoff -0.04, extent -2.599,-0.997 -2.2,-0.603
3D body: height 0.36, standoff -0.04, extent -3.399,-0.997 -3,-0.603
3D body: height 0.36, standoff -0.04, extent 0.601,-0.997 1,-0.603
3D body: height 0.36, standoff -0.04, extent 1.401,-0.997 1.8,-0.603
3D body: height 0.36, standoff -0.04, extent 2.201,-0.997 2.6,-0.603
3D body: height 0.36, standoff -0.04, extent 3.001,-0.997 3.4,-0.603
3D body: height 0.36, standoff -0.04, extent 3.801,-0.997 4.2,-0.603
3D body: height 0.36, standoff -0.04, extent -4.199,-1.797 -3.8,-1.403
3D body: height 0.36, standoff -0.04, extent -4.999,-1.797 -4.6,-1.403
3D body: height 0.36, standoff -0.04, extent -5.799,-1.797 -5.4,-1.403
3D body: height 0.36, standoff -0.04, extent -6.599,-1.797 -6.2,-1.403
3D body: height 0.36, standoff -0.04, extent -7.399,-1.797 -7,-1.403
3D body: height 0.36, standoff -0.04, extent -0.199,-1.797 0.2,-1.403
3D body: height 0.36, standoff -0.04, extent -0.999,-1.797 -0.6,-1.403
3D body: height 0.36, standoff -0.04, extent -1.799,-1.797 -1.4,-1.403
3D body: height 0.36, standoff -0.04, extent -2.599,-1.797 -2.2,-1.403
3D body: height 0.36, standoff -0.04, extent -3.399,-1.797 -3,-1.403
3D body: height 0.36, standoff -0.04, extent 0.601,-1.797 1,-1.403
3D body: height 0.36, standoff -0.04, extent 1.401,-1.797 1.8,-1.403
3D body: height 0.36, standoff -0.04, extent 2.201,-1.797 2.6,-1.403
3D body: height 0.36, standoff -0.04, extent 3.001,-1.797 3.4,-1.403
3D body: height 0.36, standoff -0.04, extent 3.801,-1.797 4.2,-1.403
3D body: height 0.36, standoff -0.04, extent 4.601,7.003 5,7.397
3D body: height 0.36, standoff -0.04, extent 5.401,7.003 5.8,7.397
3D body: height 0.36, standoff -0.04, extent 6.201,7.003 6.6,7.397
3D body: height 0.36, standoff -0.04, extent 7.001,7.003 7.4,7.397
3D body: height 0.36, standoff -0.04, extent 7.001,6.203 7.4,6.597
3D body: height 0.36, standoff -0.04, extent 6.201,6.203 6.6,6.597
3D body: height 0.36, standoff -0.04, extent 5.401,6.203 5.8,6.597
3D body: height 0.36, standoff -0.04, extent 4.601,6.203 5,6.597
3D body: height 0.36, standoff -0.04, extent 7.001,5.403 7.4,5.797
3D body: height 0.36, standoff -0.04, extent 6.201,5.403 6.6,5.797
3D body: height 0.36, standoff -0.04, extent 5.401,5.403 5.8,5.797
3D body: height 0.36, standoff -0.04, extent 4.601,5.403 5,5.797
3D body: height 0.36, standoff -0.04, extent 7.001,4.603 7.4,4.997
3D body: height 0.36, standoff -0.04, extent 6.201,4.603 6.6,4.997
3D body: height 0.36, standoff -0.04, extent 5.401,4.603 5.8,4.997
3D body: height 0.36, standoff -0.04, extent 4.601,4.603 5,4.997
3D body: height 0.36, standoff -0.04, extent 6.201,3.803 6.6,4.197
3D body: height 0.36, standoff -0.04, extent 5.401,3.803 5.8,4.197
3D body: height 0.36, standoff -0.04, extent 4.601,3.803 5,4.197
3D body: height 0.36, standoff -0.04, extent 7.001,3.003 7.4,3.397
3D body: height 0.36, standoff -0.04, extent 6.201,3.003 6.6,3.397
3D body: height 0.36, standoff -0.04, extent 5.401,3.003 5.8,3.397
3D body: height 0.36, standoff -0.04, extent 3.801,7.003 4.2,7.397
3D body: height 0.36, standoff -0.04, extent 3.001,7.003 3.4,7.397
3D body: height 0.36, standoff -0.04, extent 2.201,7.003 2.6,7.397
3D body: height 0.36, standoff -0.04, extent 1.401,7.003 1.8,7.397
3D body: height 0.36, standoff -0.04, extent 0.601,7.003 1,7.397
3D body: height 0.36, standoff -0.04, extent -3.399,7.003 -3,7.397
3D body: height 0.36, standoff -0.04, extent -2.599,7.003 -2.2,7.397
3D body: height 0.36, standoff -0.04, extent -1.799,7.003 -1.4,7.397
3D body: height 0.36, standoff -0.04, extent -0.999,7.003 -0.6,7.397
3D body: height 0.36, standoff -0.04, extent -0.199,7.003 0.2,7.397
3D body: height 0.36, standoff -0.04, extent -7.399,7.003 -7,7.397
3D body: height 0.36, standoff -0.04, extent -6.599,7.003 -6.2,7.397
3D body: height 0.36, standoff -0.04, extent -5.799,7.003 -5.4,7.397
3D body: height 0.36, standoff -0.04, extent -4.999,7.003 -4.6,7.397
3D body: height 0.36, standoff -0.04, extent -4.199,7.003 -3.8,7.397
3D body: height 0.36, standoff -0.04, extent -4.199,6.203 -3.8,6.597
3D body: height 0.36, standoff -0.04, extent -4.999,6.203 -4.6,6.597
3D body: height 0.36, standoff -0.04, extent -5.799,6.203 -5.4,6.597
3D body: height 0.36, standoff -0.04, extent -6.599,6.203 -6.2,6.597
3D body: height 0.36, standoff -0.04, extent -7.399,6.203 -7,6.597
3D body: height 0.36, standoff -0.04, extent -0.199,6.203 0.2,6.597
3D body: height 0.36, standoff -0.04, extent -0.999,6.203 -0.6,6.597
3D body: height 0.36, standoff -0.04, extent -1.799,6.203 -1.4,6.597
3D body: height 0.36, standoff -0.04, extent -2.599,6.203 -2.2,6.597
3D body: height 0.36, standoff -0.04, extent -3.399,6.203 -3,6.597
3D body: height 0.36, standoff -0.04, extent 0.601,6.203 1,6.597
3D body: height 0.36, standoff -0.04, extent 1.401,6.203 1.8,6.597
3D body: height 0.36, standoff -0.04, extent 2.201,6.203 2.6,6.597
3D body: height 0.36, standoff -0.04, extent 3.001,6.203 3.4,6.597
3D body: height 0.36, standoff -0.04, extent 3.801,6.203 4.2,6.597
3D body: height 0.36, standoff -0.04, extent -4.199,5.403 -3.8,5.797
3D body: height 0.36, standoff -0.04, extent -4.999,5.403 -4.6,5.797
3D body: height 0.36, standoff -0.04, extent -5.799,5.403 -5.4,5.797
3D body: height 0.36, standoff -0.04, extent -6.599,5.403 -6.2,5.797
3D body: height 0.36, standoff -0.04, extent -7.399,5.403 -7,5.797
3D body: height 0.36, standoff -0.04, extent -0.199,5.403 0.2,5.797
3D body: height 0.36, standoff -0.04, extent -0.999,5.403 -0.6,5.797
3D body: height 0.36, standoff -0.04, extent -1.799,5.403 -1.4,5.797
3D body: height 0.36, standoff -0.04, extent -2.599,5.403 -2.2,5.797
3D body: height 0.36, standoff -0.04, extent -3.399,5.403 -3,5.797
3D body: height 0.36, standoff -0.04, extent 0.601,5.403 1,5.797
3D body: height 0.36, standoff -0.04, extent 1.401,5.403 1.8,5.797
3D body: height 0.36, standoff -0.04, extent 2.201,5.403 2.6,5.797
3D body: height 0.36, standoff -0.04, extent 3.001,5.403 3.4,5.797
3D body: height 0.36, standoff -0.04, extent 3.801,5.403 4.2,5.797
3D body: height 0.36, standoff -0.04, extent -4.199,4.603 -3.8,4.997
3D body: height 0.36, standoff -0.04, extent -4.999,4.603 -4.6,4.997
3D body: height 0.36, standoff -0.04, extent -5.799,4.603 -5.4,4.997
3D body: height 0.36, standoff -0.04, extent -6.599,4.603 -6.2,4.997
3D body: height 0.36, standoff -0.04, extent -7.399,4.603 -7,4.997
3D body: height 0.36, standoff -0.04, extent -0.199,4.603 0.2,4.997
3D body: height 0.36, standoff -0.04, extent -0.999,4.603 -0.6,4.997
3D body: height 0.36, standoff -0.04, extent -1.799,4.603 -1.4,4.997
3D body: height 0.36, standoff -0.04, extent -2.599,4.603 -2.2,4.997
3D body: height 0.36, standoff -0.04, extent -3.399,4.603 -3,4.997
3D body: height 0.36, standoff -0.04, extent 0.601,4.603 1,4.997
3D body: height 0.36, standoff -0.04, extent 1.401,4.603 1.8,4.997
3D body: height 0.36, standoff -0.04, extent 2.201,4.603 2.6,4.997
3D body: height 0.36, standoff -0.04, extent 3.001,4.603 3.4,4.997
3D body: height 0.36, standoff -0.04, extent 3.801,4.603 4.2,4.997
3D body: height 0.36, standoff -0.04, extent -4.199,3.803 -3.8,4.197
3D body: height 0.36, standoff -0.04, extent -4.999,3.803 -4.6,4.197
3D body: height 0.36, standoff -0.04, extent -5.799,3.803 -5.4,4.197
3D body: height 0.36, standoff -0.04, extent -6.599,3.803 -6.2,4.197
3D body: height 0.36, standoff -0.04, extent -7.399,3.803 -7,4.197
3D body: height 0.36, standoff -0.04, extent -0.199,3.803 0.2,4.197
3D body: height 0.36, standoff -0.04, extent -0.999,3.803 -0.6,4.197
3D body: height 0.36, standoff -0.04, extent -1.799,3.803 -1.4,4.197
3D body: height 0.36, standoff -0.04, extent -2.599,3.803 -2.2,4.197
3D body: height 0.36, standoff -0.04, extent -3.399,3.803 -3,4.197
3D body: height 0.36, standoff -0.04, extent 0.601,3.803 1,4.197
3D body: height 0.36, standoff -0.04, extent 1.401,3.803 1.8,4.197
3D body: height 0.36, standoff -0.04, extent 2.201,3.803 2.6,4.197
3D body: height 0.36, standoff -0.04, extent 3.001,3.803 3.4,4.197
3D body: height 0.36, standoff -0.04, extent 3.801,3.803 4.2,4.197
3D body: height 0.36, standoff -0.04, extent -4.199,3.003 -3.8,3.397
3D body: height 0.36, standoff -0.04, extent -4.999,3.003 -4.6,3.397
3D body: height 0.36, standoff -0.04, extent -5.799,3.003 -5.4,3.397
3D body: height 0.36, standoff -0.04, extent -6.599,3.003 -6.2,3.397
3D body: height 0.36, standoff -0.04, extent -7.399,3.003 -7,3.397
3D body: height 0.36, standoff -0.04, extent -0.199,3.003 0.2,3.397
3D body: height 0.36, standoff -0.04, extent -0.999,3.003 -0.6,3.397
3D body: height 0.36, standoff -0.04, extent -1.799,3.003 -1.4,3.397
3D body: height 0.36, standoff -0.04, extent -2.599,3.003 -2.2,3.397
3D body: height 0.36, standoff -0.04, extent -3.399,3.003 -3,3.397
3D body: height 0.36, standoff -0.04, extent 0.601,3.003 1,3.397
3D body: height 0.36, standoff -0.04, extent 1.401,3.003 1.8,3.397
3D body: height 0.36, standoff -0.04, extent 2.201,3.003 2.6,3.397
3D body: height 0.36, standoff -0.04, extent 3.001,3.003 3.4,3.397
3D body: height 0.36, standoff -0.04, extent 3.801,3.003 4.2,3.397
3D body: height 1.3, standoff 1.29, extent -7.498,6.901 -6.9,7.499
3D body: height 1.29, standoff 0.3, extent -8.075,-8.075 8.075,8.075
